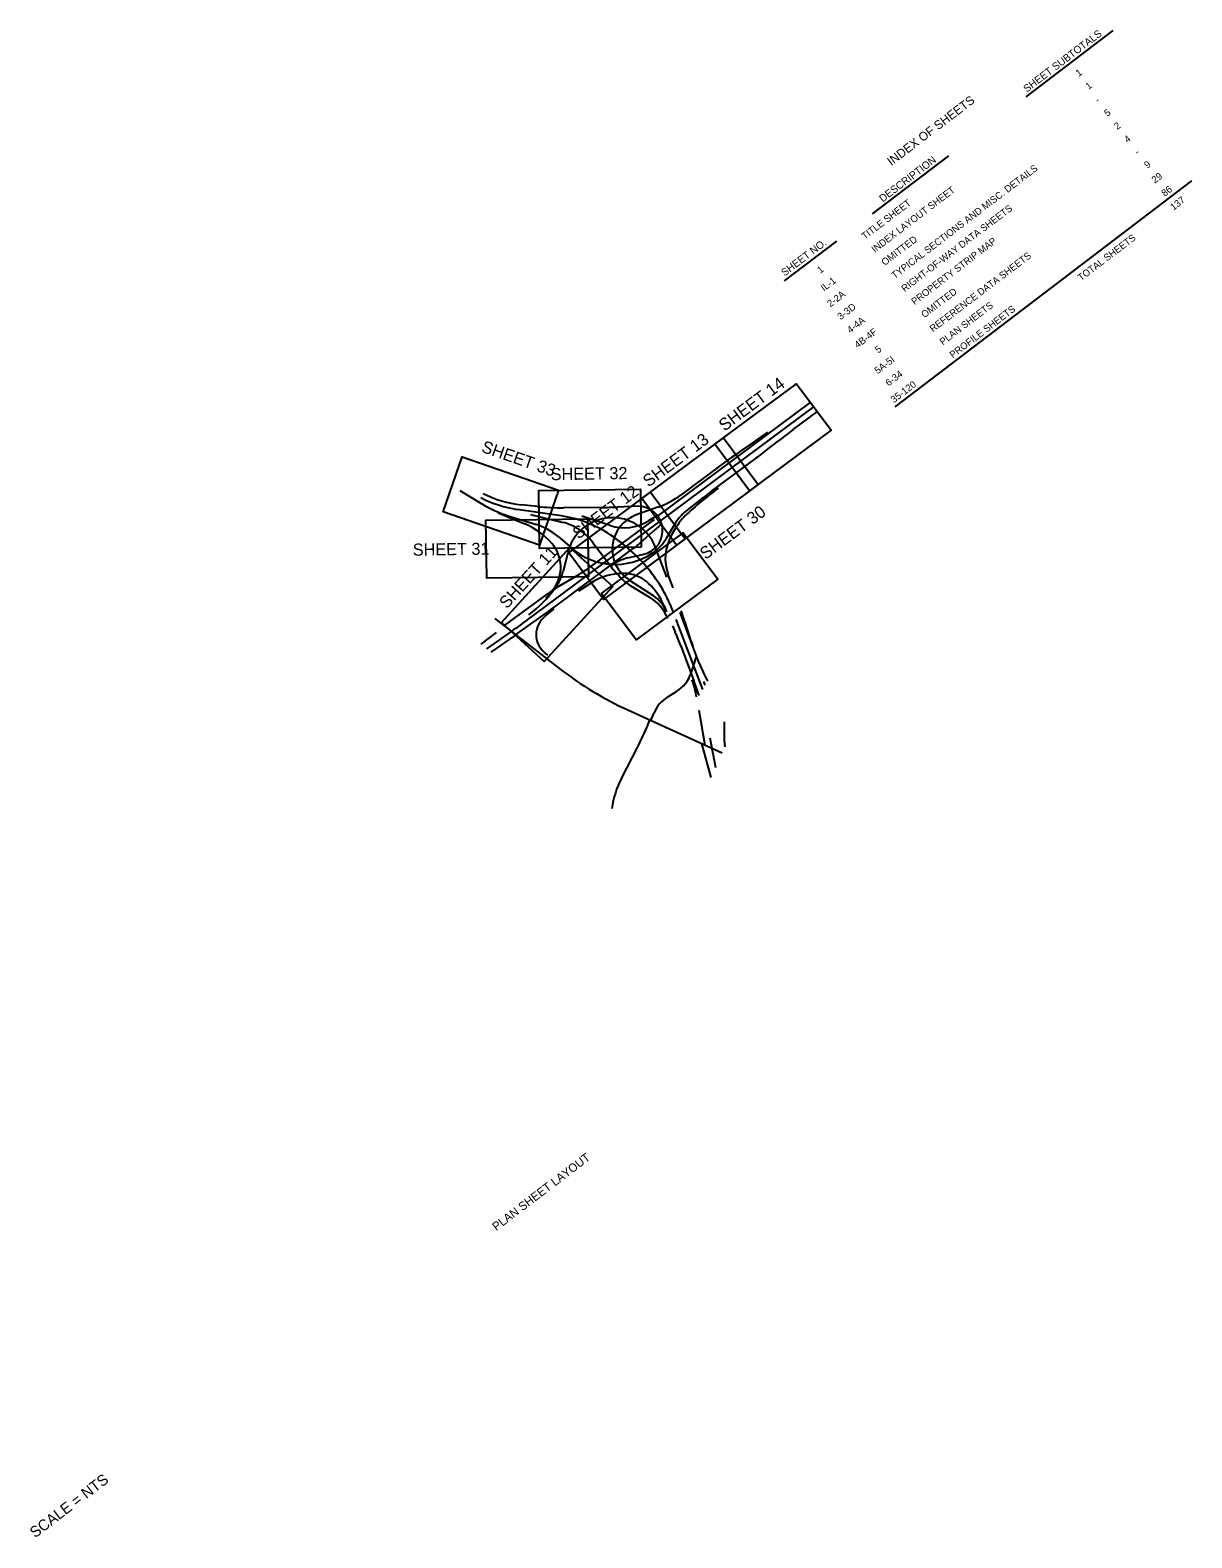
# Model space of a CAD drawing. Extents: x 1602507 to 1642884, y 1084261 to 1112516.
# Drawn here: x 1623744 to 1642884, y 1087670 to 1112516 of the extents above; entities that cross this region are included whole.
import ezdxf

# ---------------------------------------------------------------- set-up
doc = ezdxf.new("R2010")
doc.units = 0
for name, color, linetype in [('RD_EX_SU_Gas1', 7, 'Continuous'), ('RD_HC_CL', 7, 'Continuous'), ('RD_HC_SUR_Bearing_TX400', 7, 'Continuous'), ('RD_PD_GeoTech', 7, 'Continuous'), ('RD_PD_VG', 7, 'Continuous'), ('topo', 7, 'Continuous')]:
    doc.layers.add(name, color=color, linetype=linetype)

msp = doc.modelspace()

# ---------------------------------------------------------------- linework, layer by layer
at = {"layer": 'RD_HC_CL'}
for p, q in [((1636600, 1106383), (1634062, 1104496)), ((1632040, 1102873), (1636657, 1106306)), ((1636316, 1105933), (1636714, 1106229)), ((1635664, 1105725), (1635433, 1105566)), ((1635933, 1105638), (1636090, 1105761)), ((1634969, 1104917), (1635707, 1105465)), ((1635100, 1105328), (1634468, 1104860)), ((1630821, 1104932), (1631184, 1104710)), ((1632100, 1104666), (1631832, 1104694)), ((1633150, 1104651), (1632532, 1104645)), ((1633751, 1104669), (1633422, 1104657)), ((1634084, 1104654), (1633730, 1104526)), ((1631457, 1104559), (1631892, 1104379)), ((1631635, 1104507), (1632086, 1104368)), ((1632491, 1104511), (1631767, 1104619)), ((1631986, 1104532), (1632528, 1104402)), ((1633299, 1104353), (1632832, 1104504)), ((1634023, 1104452), (1632970, 1103670)), ((1634055, 1104506), (1633931, 1104429)), ((1632442, 1104172), (1632670, 1103977)), ((1633839, 1104104), (1634005, 1104255)), ((1634229, 1104146), (1634358, 1104366)), ((1634312, 1104192), (1634400, 1104341)), ((1632600, 1103905), (1632523, 1103598)), ((1633022, 1104062), (1633309, 1103684)), ((1633187, 1103607), (1633686, 1103978)), ((1634233, 1103500), (1634048, 1103990)), ((1633593, 1103818), (1633857, 1103880)), ((1632736, 1103515), (1632487, 1103370)), ((1632784, 1103278), (1632981, 1103404)), ((1632785, 1103308), (1633187, 1103607)), ((1633605, 1103460), (1634007, 1103197)), ((1634337, 1103328), (1634258, 1103539)), ((1632272, 1103230), (1631552, 1102705)), ((1632560, 1103141), (1632785, 1103308)), ((1633630, 1103366), (1633946, 1103174)), ((1631781, 1102576), (1632290, 1102943)), ((1632221, 1102851), (1632377, 1102977)), ((1634188, 1103030), (1634230, 1102930)), ((1634768, 1102085), (1634453, 1102917)), ((1631399, 1102822), (1632477, 1101988)), ((1634328, 1102700), (1634373, 1102593)), ((1634824, 1101651), (1634388, 1102804)), ((1631421, 1102590), (1631167, 1102399)), ((1631269, 1102320), (1631450, 1102448)), ((1631340, 1102265), (1631500, 1102376)), ((1632272, 1102215), (1632212, 1102267)), ((1634462, 1102370), (1634680, 1101794)), ((1634632, 1101922), (1634723, 1102194)), ((1634867, 1101724), (1634842, 1101781)), ((1634248, 1101528), (1634392, 1101618)), ((1633593, 1101314), (1635144, 1100606)), ((1633972, 1101141), (1634023, 1101263)), ((1634762, 1101307), (1634857, 1100735)), ((1633923, 1101070), (1633956, 1101147)), ((1635185, 1100787), (1635184, 1101049)), ((1633484, 1100184), (1633748, 1100693)), ((1634807, 1100758), (1634959, 1100201)), ((1634943, 1100853), (1635034, 1100365))]:
    msp.add_line(p, q, dxfattribs=at)
for centre, radius, start, end in [((1628854, 1115606), 12000, 304.5779, 305.9379), ((1643147, 1096744), 11450, 126.6256, 128.0464), ((1628876, 1114655), 11450, 306.6256, 308.0464), ((1642243, 1095686), 12000, 124.5779, 126.5281), ((1638657, 1100152), 6000, 126.6256, 133.359), ((1641800, 1095727), 11450, 126.6256, 129.2926), ((1632049, 1106508), 1910, 242.6268, 261.5065), ((1632226, 1106418), 2000, 238.6268, 252.8371), ((1632016, 1106444), 1760, 242.6268, 263.9996), ((1632497, 1108445), 3800, 263.9996, 270.537), ((1633056, 1114650), 10000, 270.537, 272.0947), ((1633765, 1104269), 400, 283.2258, 92.0947), ((1633575, 1106065), 1500, 289.8521, 306.5281), ((1632196, 1102533), 2000, 56.1301, 81.5065), ((1632351, 1103663), 760, 58.5149, 76.5065), ((1633337, 1103721), 760, 20.7167, 165.9491), ((1633532, 1105077), 760, 252.1319, 301.6256), ((1633934, 1103962), 600, 109.8521, 236.724), ((1635073, 1103948), 829, 129.2926, 149.6819), ((1635073, 1103948), 780, 133.359, 149.6819), ((1631434, 1103270), 1200, 41.0623, 67.546), ((1631791, 1103412), 1000, 49.4294, 72.8371), ((1632225, 1103458), 1000, 37.1508, 58.5149), ((1631690, 1101778), 2909, 39.6334, 56.1301), ((1633573, 1104529), 760, 303.6278, 329.6819), ((1635351, 1102775), 2000, 126.6256, 132.2944), ((1634968, 1103808), 760, 149.6819, 200.7167), ((1631886, 1103664), 600, 323.5746, 41.0623), ((1633385, 1104812), 1100, 229.4294, 303.6278), ((1632493, 1105583), 2000, 306.6256, 312.2944), ((1631479, 1105676), 2500, 300.2008, 306.6256), ((1633767, 1103078), 760, 103.2258, 127.6045), ((1634903, 1104892), 2000, 217.1508, 224.9911), ((1631747, 1103792), 800, 324.5024, 345.9491), ((1633520, 1102562), 1000, 90.0249, 122.6256), ((1634026, 1104015), 760, 224.9911, 238.635), ((1633520, 1102962), 600, 46.3737, 90.0249), ((1632004, 1102039), 2500, 20.7167, 39.6334), ((1630770, 1104489), 2000, 306.4947, 324.5024), ((1630775, 1104484), 1981, 317.7887, 323.5746), ((1633744, 1101209), 2500, 120.2008, 126.0872), ((1633175, 1102600), 1100, 23.0073, 46.3737), ((1633550, 1102525), 760, 23.0073, 58.635), ((1633678, 1102695), 600, 23.0073, 56.724), ((1618838, 1121599), 23000, 305.7928, 306.6256), ((1626855, 1100498), 8000, 16.5502, 17.819), ((1616287, 1124065), 26405, 305.0468, 306.6256), ((1632460, 1102555), 380, 128.8796, 229.2983), ((1640275, 1104486), 6000, 196.5502, 200.7167), ((1616287, 1124065), 26492, 305.0468, 305.7928), ((1628839, 1100243), 6012, 20.7167, 23.0073), ((1635946, 1106472), 5670, 232.2721, 245.4744), ((1634092, 1102102), 570, 301.8419, 341.5484), ((1636639, 1102792), 2000, 200.7167, 209.9855), ((1633245, 1101280), 1500, 9.5074, 20.7167), ((1629536, 1099848), 5500, 18.0335, 20.7167), ((1634549, 1101044), 570, 121.8419, 157.379), ((1629308, 1102993), 5000, 332.6108, 337.379), ((1634184, 1101043), 1000, 0.3042, 4.1214), ((1636150, 1100792), 965, 180.3042, 185.1972), ((1634819, 1099493), 1503, 152.6108, 172.4975)]:
    msp.add_arc(centre, radius, start, end, dxfattribs=at)
at = {"layer": 'RD_PD_VG'}
for p, q in [((1640153, 1111415), (1641590, 1112510)), ((1640153, 1111415), (1641590, 1112510)), ((1637624, 1109489), (1638879, 1110445)), ((1637624, 1109489), (1638879, 1110445)), ((1637998, 1106308), (1642884, 1110030)), ((1636171, 1108383), (1637034, 1109039)), ((1636171, 1108383), (1637034, 1109039))]:
    msp.add_line(p, q, dxfattribs=at)
at = {"layer": 'topo'}
for points in [[(1635027, 1105691), (1636372, 1106690), (1636942, 1105923), (1635598, 1104924)], [(1633823, 1104796), (1635168, 1105796), (1635738, 1105028), (1634394, 1104029)], [(1632134, 1104031), (1630551, 1104579), (1630864, 1105483), (1632447, 1104935)], [(1633813, 1103997), (1632138, 1103972), (1632124, 1104928), (1633799, 1104953)], [(1632620, 1103901), (1633964, 1104901), (1634534, 1104133), (1633190, 1103134)], [(1632941, 1103509), (1631266, 1103484), (1631252, 1104440), (1632927, 1104465)], [(1633158, 1103234), (1634503, 1104234), (1635073, 1103466), (1633729, 1102467)], [(1631508, 1102754), (1632635, 1103993), (1633342, 1103349), (1632215, 1102110)]]:
    msp.add_lwpolyline(points, close=True, dxfattribs=at)

# ---------------------------------------------------------------- texts
at = {"layer": 'RD_EX_SU_Gas1'}
msp.add_text('PLAN SHEET LAYOUT', height=139.67, rotation=37.3059, dxfattribs=at).set_placement((1631424, 1092722))
at = {"layer": 'RD_HC_SUR_Bearing_TX400'}
for s, rotation, p in [('SHEET 14', 36.6256, (1635183, 1105897)), ('SHEET 33', 340.9029, (1631164, 1105569)), ('SHEET 13', 36.6256, (1633932, 1104976)), ('SHEET 32', 0.8477, (1632322, 1105099)), ('SHEET 12', 36.6256, (1632775, 1104118)), ('SHEET 30', 36.6256, (1634871, 1103782)), ('SHEET 31', 0.8477, (1630049, 1103854)), ('SHEET 11', 47.7138, (1631599, 1102969))]:
    msp.add_text(s, height=200, rotation=rotation, dxfattribs=at).set_placement(p)
at = {"layer": 'RD_PD_GeoTech'}
msp.add_text('SCALE = NTS', height=180, rotation=37.3059, dxfattribs=at).set_placement((1623824, 1087660))
at = {"layer": 'RD_PD_VG'}
for s, height, rotation, p in [('SHEET SUBTOTALS', 122.78, 37.3048, (1640166, 1111484)), ('SHEET SUBTOTALS', 122.78, 37.3048, (1640166, 1111484)), ('1', 114, 37.3059, (1641020, 1111746)), ('1', 114, 37.3059, (1641020, 1111746)), ('1', 114, 37.3059, (1641183, 1111531)), ('1', 114, 37.3059, (1641183, 1111531)), ('INDEX OF SHEETS', 145.01, 37.3048, (1637932, 1110275)), ('INDEX OF SHEETS', 145.01, 37.3048, (1637932, 1110275)), ('-', 114, 37.3059, (1641338, 1111309)), ('-', 114, 37.3059, (1641338, 1111309)), ('5', 114, 37.3059, (1641491, 1111085)), ('5', 114, 37.3059, (1641491, 1111085)), ('2', 114, 37.3059, (1641656, 1110869)), ('4', 114, 37.3059, (1641820, 1110654)), ('DESCRIPTION', 122.78, 37.3048, (1637791, 1109674)), ('DESCRIPTION', 122.78, 37.3048, (1637791, 1109674)), ('-', 114, 37.3059, (1641991, 1110451)), ('-', 114, 37.3059, (1641991, 1110451)), ('9', 114, 37.3059, (1642151, 1110231)), ('TYPICAL SECTIONS AND MISC. DETAILS', 114.5, 37.3059, (1637987, 1108412)), ('TYPICAL SECTIONS AND MISC. DETAILS', 114.5, 37.3059, (1637987, 1108412)), ('29', 114.5, 37.3059, (1642274, 1109984)), ('INDEX LAYOUT SHEET', 114.5, 37.3059, (1637659, 1108843)), ('INDEX LAYOUT SHEET', 114.5, 37.3059, (1637659, 1108843)), ('86', 114.5, 37.3059, (1642436, 1109768)), ('TITLE SHEET', 114.5, 37.3059, (1637496, 1109058)), ('TITLE SHEET', 114.5, 37.3059, (1637496, 1109058)), ('RIGHT-OF-WAY DATA SHEETS', 114.5, 37.3059, (1638152, 1108196)), ('RIGHT-OF-WAY DATA SHEETS', 114.5, 37.3059, (1638152, 1108196)), ('137', 114.5, 37.3059, (1642581, 1109539)), ('OMITTED', 114.5, 37.3059, (1637823, 1108628)), ('OMITTED', 114.5, 37.3059, (1637823, 1108628)), ('TOTAL SHEETS', 114.5, 37.3059, (1641058, 1108376)), ('SHEET NO.', 122.8, 37.3048, (1636175, 1108454)), ('SHEET NO.', 122.8, 37.3048, (1636175, 1108454)), ('PROPERTY STRIP MAP', 114.5, 37.3059, (1638316, 1107981)), ('PROPERTY STRIP MAP', 114.5, 37.3059, (1638316, 1107981)), ('1', 114, 37.3059, (1636763, 1108500)), ('1', 114, 37.3059, (1636763, 1108500)), ('REFERENCE DATA SHEETS', 114.5, 37.3059, (1638618, 1107534)), ('IL-1', 114.5, 37.3059, (1636823, 1108206)), ('IL-1', 114.5, 37.3059, (1636823, 1108206)), ('2-2A', 114.5, 37.3059, (1636928, 1107946)), ('2-2A', 114.5, 37.3059, (1636928, 1107946)), ('OMITTED', 114.5, 37.3059, (1638478, 1107767)), ('OMITTED', 114.5, 37.3059, (1638478, 1107767)), ('3-3D', 114.5, 37.3059, (1637097, 1107734)), ('3-3D', 114.5, 37.3059, (1637097, 1107734)), ('PLAN SHEETS', 114.5, 37.3059, (1638782, 1107319)), ('PROFILE SHEETS', 114.5, 37.3059, (1638946, 1107104)), ('4-4A', 114.5, 37.3059, (1637255, 1107515)), ('4B-4F', 114.5, 37.3059, (1637378, 1107269)), ('5A-5I', 114.5, 37.3059, (1637708, 1106843)), ('5', 114, 37.3059, (1637716, 1107186)), ('6-34', 114.5, 37.3059, (1637889, 1106641)), ('35-120', 114.5, 37.3059, (1637975, 1106366))]:
    msp.add_text(s, height=height, rotation=rotation, dxfattribs=at).set_placement(p)

doc.saveas('drawing.dxf')
